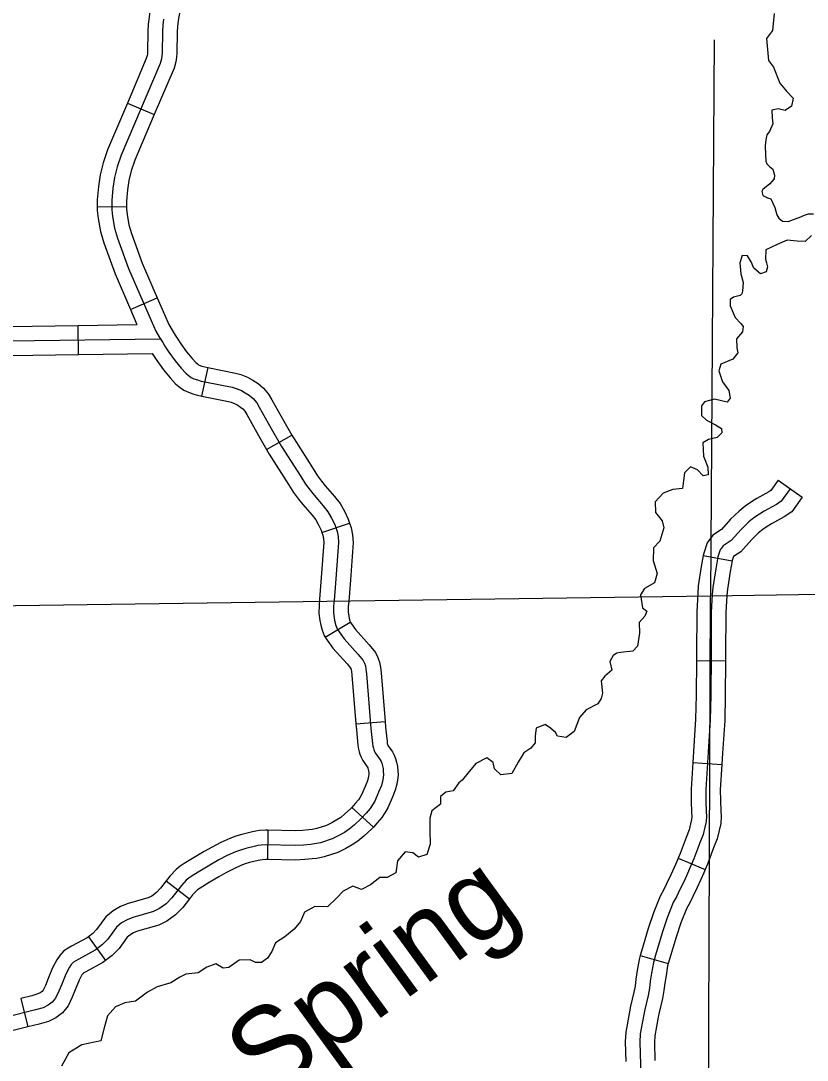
# Model space of a CAD drawing. Extents: x -492261 to -432772, y 1441225 to 1452922.
# Drawn here: x -458346.3 to -458231, y 1451481.9 to 1451634.2 of the extents above; entities that cross this region are included whole.
import ezdxf

# ---------------------------------------------------------------- set-up
doc = ezdxf.new("R2010")
doc.units = 0
doc.layers.add('Default', color=7, linetype='Continuous')

msp = doc.modelspace()

# ---------------------------------------------------------------- linework, layer by layer
at = {"layer": 'Default'}
for p, q in [((-458330.65, 1451622.14), (-458326.71, 1451620.45)), ((-458335.06, 1451606.95), (-458330.78, 1451606.97)), ((-458330.2, 1451591.87), (-458326.27, 1451593.57)), ((-458337.82, 1451585.27), (-458337.88, 1451589.56)), ((-458319.75, 1451579.19), (-458318.82, 1451583.37)), ((-458310.25, 1451571.35), (-458306.54, 1451573.48)), ((-458235.25, 1451566.86), (-458231.75, 1451564.38)), ((-458302.13, 1451559.2), (-458298.07, 1451560.57)), ((-458246.23, 1451555.82), (-458242.01, 1451555.05)), ((-458301.64, 1451543.85), (-458297.97, 1451546.08)), ((-458247.24, 1451540.43), (-458242.96, 1451540.39)), ((-458297.15, 1451531.15), (-458292.88, 1451531.5)), ((-458247.77, 1451525.48), (-458243.49, 1451525.2)), ((-458297.75, 1451518.91), (-458294.59, 1451516.02)), ((-458310.04, 1451515.55), (-458310.13, 1451511.27)), ((-458249.9, 1451511.46), (-458245.95, 1451509.8)), ((-458324.95, 1451508.13), (-458321.56, 1451505.5)), ((-458336.37, 1451499.93), (-458333.84, 1451496.48)), ((-458255.48, 1451497.21), (-458251.36, 1451496.03)), ((-458346.27, 1451490.91), (-458345.25, 1451486.75))]:
    msp.add_line(p, q, dxfattribs=at)
for points in [[(-458327.21, 1451636.18), (-458327.27, 1451635.9), (-458327.39, 1451635.26), (-458327.47, 1451634.71), (-458327.58, 1451633.7), (-458327.63, 1451632.69), (-458327.7, 1451629.6), (-458327.72, 1451629.3), (-458327.75, 1451629.09), (-458327.87, 1451628.65), (-458330.65, 1451622.14)], [(-458323.01, 1451635.29), (-458323.07, 1451635.04), (-458323.17, 1451634.53), (-458323.22, 1451634.17), (-458323.31, 1451633.38), (-458323.34, 1451632.55), (-458323.42, 1451629.45), (-458323.45, 1451628.84), (-458323.56, 1451628.18), (-458323.81, 1451627.24), (-458326.71, 1451620.45)], [(-458325.35, 1451634.44), (-458325.45, 1451633.54), (-458325.48, 1451632.62), (-458325.56, 1451629.52)], [(-458235.82, 1451635.25), (-458236.08, 1451632.75), (-458236.94, 1451631.62), (-458236.67, 1451628.39), (-458235.94, 1451627.4), (-458235.03, 1451625.07), (-458234.01, 1451623.88), (-458233.07, 1451622.84), (-458233.28, 1451621.66), (-458234.21, 1451621.07), (-458235.24, 1451621.31), (-458236.18, 1451621.09), (-458236.12, 1451619.95), (-458236.02, 1451619.09), (-458236.51, 1451617.99), (-458236.9, 1451617.47), (-458237.08, 1451616.75), (-458237.18, 1451615.86), (-458237.18, 1451615.71)], [(-458244.61, 1451631.4), (-458245.17, 1451549.93)], [(-458325.56, 1451629.52), (-458325.58, 1451629.07), (-458325.66, 1451628.63), (-458325.84, 1451627.94), (-458331.57, 1451614.52)], [(-458330.65, 1451622.14), (-458333.58, 1451615.27), (-458334.2, 1451613.37), (-458334.62, 1451611.64), (-458334.9, 1451609.93), (-458335.07, 1451607.94), (-458335.06, 1451606.95)], [(-458326.71, 1451620.45), (-458329.56, 1451613.77), (-458330.07, 1451612.2), (-458330.42, 1451610.78), (-458330.65, 1451609.41), (-458330.78, 1451607.77), (-458330.78, 1451606.97)], [(-458331.57, 1451614.52), (-458332.13, 1451612.79), (-458332.52, 1451611.21), (-458332.77, 1451609.67), (-458332.92, 1451607.86), (-458332.92, 1451606.51), (-458332.82, 1451605.53), (-458332.52, 1451603.82), (-458332.09, 1451602.33), (-458330.47, 1451597.88), (-458327.18, 1451590.27), (-458326.46, 1451588.72), (-458325.94, 1451587.79), (-458325.47, 1451587.03), (-458325.08, 1451586.38), (-458324.59, 1451585.63), (-458323.65, 1451584.35), (-458322.77, 1451583.28), (-458322.07, 1451582.55), (-458321.75, 1451582.25), (-458321.28, 1451581.91), (-458320.9, 1451581.74), (-458320.39, 1451581.56), (-458319.83, 1451581.4), (-458319.06, 1451581.23), (-458315.3, 1451580.48), (-458314.72, 1451580.31), (-458313.93, 1451580.01), (-458313.36, 1451579.69), (-458312.78, 1451579.31), (-458312.23, 1451578.84), (-458311.69, 1451578.22), (-458311.31, 1451577.58), (-458309.57, 1451574.46), (-458308.04, 1451571.8), (-458305.24, 1451567.39), (-458304.54, 1451566.3), (-458303.87, 1451565.39), (-458303.28, 1451564.66), (-458301.93, 1451563.11), (-458301.25, 1451562.24), (-458300.71, 1451561.31), (-458300.26, 1451560.35), (-458299.92, 1451559.36), (-458299.77, 1451558.59), (-458299.7, 1451557.73), (-458300.08, 1451552.41), (-458300.34, 1451549.25), (-458300.41, 1451548.45), (-458300.41, 1451547.47), (-458300.34, 1451546.64), (-458300.22, 1451546.09), (-458300.08, 1451545.56), (-458299.88, 1451545.09), (-458299.6, 1451544.62), (-458298.86, 1451543.61), (-458296.83, 1451541.34), (-458296.09, 1451540.44), (-458295.91, 1451540.07), (-458295.75, 1451539.64), (-458295.67, 1451539.17), (-458295.61, 1451538.47), (-458294.95, 1451530.46), (-458294.72, 1451528.28), (-458294.66, 1451527.86), (-458294.59, 1451527.6), (-458294.53, 1451527.37), (-458294.43, 1451527.12), (-458294.31, 1451526.89), (-458293.61, 1451525.88), (-458293.47, 1451525.64), (-458293.36, 1451525.37), (-458293.26, 1451525.01), (-458293.17, 1451524.6), (-458293.13, 1451524.17), (-458293.12, 1451523.71), (-458293.16, 1451523.22), (-458293.24, 1451522.76), (-458293.42, 1451522.12), (-458293.82, 1451521.12), (-458294.39, 1451519.81), (-458294.7, 1451519.27), (-458295.08, 1451518.73), (-458295.63, 1451518.05), (-458296.36, 1451517.26), (-458297.4, 1451516.29), (-458298.12, 1451515.7), (-458298.82, 1451515.25), (-458299.64, 1451514.78), (-458300.63, 1451514.29), (-458302.32, 1451513.73), (-458303.22, 1451513.56), (-458303.8, 1451513.49), (-458304.82, 1451513.39), (-458305.98, 1451513.32), (-458310.33, 1451513.42), (-458311.06, 1451513.37), (-458311.52, 1451513.3), (-458311.89, 1451513.24)], [(-458237.18, 1451615.71), (-458237.07, 1451613.62), (-458236.91, 1451613.25), (-458236.5, 1451612.83), (-458236.04, 1451612.44), (-458235.81, 1451611.56), (-458235.86, 1451611.04), (-458236.47, 1451610.28), (-458237.5, 1451609.48), (-458237.64, 1451609.16), (-458237.51, 1451608.59), (-458236.82, 1451608.26), (-458236.32, 1451608.08), (-458235.75, 1451606.83), (-458235.46, 1451605.75), (-458235.14, 1451605.27), (-458234.61, 1451604.85), (-458233.75, 1451604.78), (-458233.13, 1451605), (-458232.17, 1451605.37), (-458231.4, 1451605.7), (-458230.81, 1451605.89), (-458230.06, 1451605.91)], [(-458335.06, 1451606.95), (-458335.06, 1451606.39), (-458334.94, 1451605.23), (-458334.61, 1451603.33), (-458334.12, 1451601.67), (-458332.46, 1451597.09), (-458330.2, 1451591.87)], [(-458330.78, 1451606.97), (-458330.77, 1451606.62), (-458330.69, 1451605.82), (-458330.43, 1451604.3), (-458330.05, 1451603), (-458328.47, 1451598.67), (-458326.27, 1451593.57)], [(-458230.38, 1451602.75), (-458231.28, 1451601.83), (-458232.48, 1451601.89), (-458233.91, 1451602.03), (-458235.38, 1451601.39), (-458237.05, 1451600.63), (-458237.1, 1451599.25), (-458236.97, 1451598.74), (-458236.84, 1451598.14), (-458237.03, 1451597.42), (-458237.82, 1451597.11), (-458238.81, 1451597.92), (-458239.21, 1451598.86), (-458239.74, 1451599.73), (-458240.52, 1451599.8), (-458240.89, 1451598.7), (-458240.74, 1451597.13), (-458240.39, 1451595.82), (-458240.47, 1451594.58), (-458240.6, 1451594.18), (-458240.8, 1451593.91), (-458241.79, 1451593.69), (-458242.27, 1451593.36), (-458242.3, 1451592.41), (-458241.55, 1451590.71), (-458240.72, 1451589.81), (-458240.4, 1451589.39), (-458240.49, 1451588.59), (-458241.38, 1451587.59), (-458241.32, 1451586.24), (-458241.16, 1451585.53), (-458241.88, 1451584.62), (-458243.66, 1451583.86), (-458243.95, 1451582.91), (-458243.42, 1451581.26), (-458242.47, 1451580.02), (-458242.3, 1451578.91), (-458242.75, 1451578.32), (-458244.59, 1451578.74), (-458246.06, 1451578.33), (-458246.51, 1451577.77), (-458246.47, 1451576.37), (-458245.77, 1451575.64), (-458244.43, 1451574.98), (-458243.56, 1451574.46), (-458243.52, 1451573.8), (-458244.19, 1451573.1), (-458245.44, 1451572.84), (-458246.28, 1451572.33), (-458246.18, 1451570.41), (-458245.56, 1451568.76), (-458245.51, 1451567.67), (-458246.27, 1451567.51), (-458247.07, 1451568.38), (-458248.08, 1451568.81), (-458248.97, 1451567.96), (-458249.14, 1451566.81), (-458249.26, 1451565.66), (-458250.71, 1451565.48), (-458252.13, 1451564.96), (-458253.3, 1451563.69), (-458253.23, 1451562.12), (-458252.28, 1451560.91), (-458252.03, 1451559.86), (-458252.58, 1451557.92), (-458253.55, 1451556.95), (-458253.59, 1451555.09), (-458253, 1451553.18), (-458253.4, 1451551.82), (-458254.83, 1451551.01), (-458255.41, 1451550.08), (-458255.16, 1451548.16), (-458254.52, 1451547.66), (-458254.79, 1451546.94), (-458255.62, 1451546), (-458255.58, 1451544.45), (-458255.85, 1451542.53), (-458256.54, 1451541.79), (-458258.37, 1451541.63), (-458258.91, 1451541.5), (-458259.44, 1451541.18), (-458259.91, 1451540.3), (-458259.62, 1451539.02), (-458260.68, 1451538.13), (-458261.21, 1451537.46), (-458261.02, 1451535.66)], [(-458326.27, 1451593.57), (-458325.22, 1451591.15), (-458324.55, 1451589.69), (-458324.09, 1451588.87), (-458323.64, 1451588.14), (-458323.27, 1451587.51), (-458322.83, 1451586.85), (-458321.96, 1451585.66), (-458321.17, 1451584.7), (-458320.57, 1451584.08), (-458320.39, 1451583.91), (-458320.21, 1451583.78), (-458320.11, 1451583.73), (-458319.73, 1451583.6), (-458319.31, 1451583.48), (-458318.82, 1451583.37)], [(-458330.2, 1451591.87), (-458329.26, 1451589.68)], [(-458352.96, 1451589.34), (-458347.96, 1451589.41), (-458337.88, 1451589.56)], [(-458337.88, 1451589.56), (-458329.26, 1451589.68)], [(-458410.2, 1451575.22), (-458403.22, 1451580.02), (-458402.02, 1451580.8), (-458400.68, 1451581.37), (-458399.83, 1451581.69), (-458398.9, 1451581.96), (-458397.46, 1451582.27), (-458392.1, 1451583.36), (-458391.17, 1451583.61), (-458390.31, 1451583.87), (-458389.44, 1451584.26), (-458387.87, 1451584.99), (-458385.99, 1451586), (-458384.07, 1451587.06), (-458383.46, 1451587.37), (-458382.88, 1451587.6), (-458382.48, 1451587.73), (-458382.03, 1451587.79), (-458381, 1451587.85), (-458363.94, 1451587.3), (-458355.27, 1451587.17), (-458347.93, 1451587.27), (-458325.82, 1451587.59)], [(-458337.82, 1451585.27), (-458327.03, 1451585.43)], [(-458327.03, 1451585.43), (-458326.35, 1451584.41), (-458325.35, 1451583.03), (-458324.37, 1451581.85), (-458323.57, 1451581.01), (-458323.12, 1451580.6), (-458322.35, 1451580.04), (-458321.69, 1451579.75), (-458321.04, 1451579.51), (-458320.35, 1451579.32), (-458319.75, 1451579.19)], [(-458352.9, 1451585.06), (-458347.9, 1451585.12), (-458337.82, 1451585.27)], [(-458318.82, 1451583.37), (-458318.62, 1451583.33), (-458314.78, 1451582.56), (-458314.04, 1451582.34), (-458313.03, 1451581.96), (-458312.24, 1451581.52), (-458311.49, 1451581.02), (-458310.71, 1451580.36), (-458309.95, 1451579.48), (-458309.45, 1451578.65), (-458307.7, 1451575.51), (-458306.54, 1451573.48)], [(-458319.75, 1451579.19), (-458319.5, 1451579.13), (-458315.81, 1451578.4), (-458315.41, 1451578.28), (-458314.84, 1451578.06), (-458314.47, 1451577.86), (-458314.07, 1451577.59), (-458313.74, 1451577.31), (-458313.43, 1451576.96), (-458313.16, 1451576.5), (-458311.43, 1451573.4), (-458310.25, 1451571.35)], [(-458306.54, 1451573.48), (-458306.21, 1451572.91), (-458303.43, 1451568.55), (-458302.77, 1451567.51), (-458302.17, 1451566.7), (-458301.64, 1451566.04), (-458300.28, 1451564.48), (-458299.47, 1451563.44), (-458298.81, 1451562.31), (-458298.26, 1451561.15), (-458298.07, 1451560.57)], [(-458310.25, 1451571.35), (-458309.87, 1451570.69), (-458307.05, 1451566.24), (-458306.3, 1451565.08), (-458305.57, 1451564.09), (-458304.92, 1451563.28), (-458303.58, 1451561.75), (-458303.03, 1451561.04), (-458302.61, 1451560.32), (-458302.25, 1451559.55), (-458302.13, 1451559.2)], [(-458233.5, 1451565.62), (-458234.8, 1451563.78), (-458235.5, 1451563.31), (-458237.3, 1451562.31), (-458238.01, 1451561.9), (-458238.8, 1451561.36), (-458239.55, 1451560.74), (-458240.67, 1451559.65), (-458242.14, 1451558.01), (-458243.32, 1451557.23), (-458243.74, 1451556.68), (-458244.08, 1451555.64), (-458244.41, 1451553.85), (-458244.83, 1451551.14), (-458244.92, 1451550.11), (-458245.05, 1451547.53), (-458245.09, 1451541.33), (-458245.14, 1451535.34), (-458245.22, 1451531.75), (-458245.53, 1451526.98), (-458245.87, 1451521.53), (-458245.86, 1451519.89), (-458245.82, 1451518.26), (-458245.77, 1451517.6), (-458245.81, 1451516.85), (-458245.99, 1451516.02), (-458246.25, 1451514.95), (-458246.73, 1451513.73), (-458247.62, 1451511.36), (-458248.13, 1451510.14), (-458248.54, 1451509.22), (-458249.05, 1451508.08), (-458249.7, 1451506.78), (-458250.11, 1451505.91), (-458250.63, 1451504.98), (-458251.52, 1451502.72), (-458252.26, 1451500.52), (-458253.24, 1451497.26), (-458253.55, 1451496.16), (-458253.8, 1451494.63), (-458254, 1451493.45), (-458254.11, 1451492.39), (-458254.32, 1451491.35), (-458254.81, 1451489.3), (-458254.96, 1451488.55), (-458255.46, 1451485.7), (-458255.54, 1451484.5), (-458255.28, 1451476.27)], [(-458235.25, 1451566.86), (-458236.32, 1451565.34), (-458236.62, 1451565.14), (-458238.37, 1451564.17), (-458239.16, 1451563.7), (-458240.08, 1451563.08), (-458240.98, 1451562.34), (-458242.22, 1451561.13), (-458243.55, 1451559.65), (-458244.81, 1451558.82), (-458245.66, 1451557.68), (-458246.16, 1451556.17), (-458246.23, 1451555.82)], [(-458231.75, 1451564.38), (-458233.27, 1451562.23), (-458234.38, 1451561.48), (-458236.24, 1451560.45), (-458236.86, 1451560.09), (-458237.51, 1451559.64), (-458238.12, 1451559.14), (-458239.12, 1451558.17), (-458240.73, 1451556.37), (-458241.82, 1451555.66), (-458242, 1451555.1), (-458242.01, 1451555.05)], [(-458298.07, 1451560.57), (-458297.85, 1451559.9), (-458297.65, 1451558.88), (-458297.55, 1451557.73), (-458297.95, 1451552.25), (-458298.21, 1451549.07), (-458298.27, 1451548.35), (-458298.27, 1451547.57), (-458298.21, 1451546.96), (-458298.13, 1451546.58), (-458298.05, 1451546.26), (-458297.97, 1451546.07), (-458297.97, 1451546.08)], [(-458302.13, 1451559.2), (-458302, 1451558.81), (-458301.9, 1451558.29), (-458301.85, 1451557.72), (-458302.22, 1451552.58), (-458302.48, 1451549.43), (-458302.55, 1451548.54), (-458302.56, 1451547.37), (-458302.46, 1451546.32), (-458302.31, 1451545.6), (-458302.11, 1451544.86), (-458301.79, 1451544.11), (-458301.64, 1451543.85)], [(-458246.23, 1451555.82), (-458246.52, 1451554.21), (-458246.96, 1451551.4), (-458247.05, 1451550.26), (-458247.19, 1451547.59), (-458247.24, 1451541.35), (-458247.24, 1451540.43)], [(-458242.01, 1451555.05), (-458242.3, 1451553.49), (-458242.7, 1451550.89), (-458242.78, 1451549.96), (-458242.91, 1451547.46), (-458242.95, 1451541.32), (-458242.96, 1451540.39)], [(-458686.04, 1451548.16), (-458545.7, 1451551.4), (-458396.3, 1451547.82), (-458245.17, 1451549.93), (-458096.72, 1451552.17), (-457948.01, 1451552.92)], [(-458245.97, 1451139.54), (-458246.91, 1451249.54), (-458245.74, 1451399.02), (-458245.17, 1451549.93)], [(-458297.97, 1451546.08), (-458297.81, 1451545.81), (-458297.19, 1451544.96), (-458295.2, 1451542.73), (-458294.27, 1451541.61), (-458293.93, 1451540.9), (-458293.67, 1451540.19), (-458293.54, 1451539.45), (-458293.47, 1451538.65), (-458292.88, 1451531.5)], [(-458301.64, 1451543.85), (-458301.38, 1451543.43), (-458300.52, 1451542.26), (-458298.45, 1451539.94), (-458297.9, 1451539.27), (-458297.88, 1451539.23), (-458297.83, 1451539.09), (-458297.8, 1451538.89), (-458297.74, 1451538.29), (-458297.15, 1451531.15)], [(-458247.24, 1451540.43), (-458247.28, 1451535.37), (-458247.36, 1451531.84), (-458247.67, 1451527.12), (-458247.77, 1451525.48)], [(-458242.96, 1451540.39), (-458243, 1451535.3), (-458243.08, 1451531.66), (-458243.39, 1451526.85), (-458243.49, 1451525.2)], [(-458261.02, 1451535.66), (-458261.2, 1451534.85), (-458261.69, 1451534.09), (-458263.42, 1451533.19), (-458264.36, 1451532.08), (-458265.14, 1451530.05), (-458266.32, 1451529.13), (-458267.61, 1451529.33), (-458267.91, 1451529.9), (-458268.61, 1451530.54), (-458269.42, 1451531.06), (-458270.73, 1451530.52), (-458270.87, 1451529.42), (-458270.87, 1451528.39), (-458271.51, 1451527.57), (-458272.52, 1451526.92), (-458273.35, 1451525.55), (-458274.28, 1451523.89), (-458275.9, 1451523.68), (-458276.81, 1451524.57), (-458277.03, 1451525.51), (-458277.94, 1451526.18), (-458279.58, 1451525.36), (-458280.74, 1451523.93), (-458281.57, 1451522.91), (-458282.08, 1451522.52), (-458282.9, 1451521.35), (-458283.99, 1451521.15), (-458284.74, 1451520.5), (-458284.74, 1451519.36), (-458286, 1451518.41), (-458286.32, 1451517.34), (-458286.3, 1451515.48), (-458286.28, 1451513.53), (-458286.76, 1451512.02), (-458287.95, 1451511.62), (-458288.79, 1451512.23), (-458289.94, 1451512.4), (-458291.05, 1451511.06), (-458291.29, 1451509.3), (-458292.59, 1451508.61), (-458293.65, 1451508.64), (-458294.99, 1451507.57), (-458296.32, 1451506.88), (-458297.59, 1451507.34), (-458299, 1451506.64), (-458299.98, 1451505.59), (-458301.29, 1451504.35), (-458303.18, 1451504.39), (-458304.7, 1451503.55), (-458305.29, 1451502.19), (-458306.18, 1451501.07), (-458307.55, 1451499.92), (-458308.93, 1451499.06), (-458309.47, 1451497.78), (-458310.13, 1451496.79), (-458311, 1451496.17), (-458311.89, 1451496.17), (-458312.64, 1451496.56), (-458314.25, 1451496.54), (-458315.79, 1451495.45), (-458316.59, 1451495.34), (-458317.69, 1451495.97), (-458319.02, 1451495.51), (-458320.26, 1451494.67), (-458322.09, 1451494.46), (-458322.96, 1451494.03), (-458324.26, 1451493.2), (-458326.3, 1451492.6), (-458327.71, 1451491.85), (-458329.45, 1451490.49), (-458331.02, 1451490.28), (-458332.4, 1451489.7), (-458333.54, 1451488.35), (-458334.07, 1451486.62), (-458334.53, 1451484.69), (-458337.32, 1451484.1), (-458339.21, 1451482.93), (-458340.3, 1451480.99)], [(-458297.15, 1451531.15), (-458297.08, 1451530.26), (-458296.85, 1451528.01), (-458296.76, 1451527.45), (-458296.66, 1451527.04), (-458296.56, 1451526.7), (-458296.4, 1451526.25), (-458296.15, 1451525.78), (-458295.41, 1451524.72), (-458295.41, 1451524.71), (-458295.39, 1451524.67), (-458295.33, 1451524.48), (-458295.29, 1451524.27), (-458295.27, 1451524.04), (-458295.26, 1451523.78), (-458295.29, 1451523.49), (-458295.33, 1451523.23), (-458295.45, 1451522.82), (-458295.8, 1451521.95), (-458296.31, 1451520.76), (-458296.51, 1451520.42), (-458296.78, 1451520.03), (-458297.25, 1451519.46), (-458297.75, 1451518.91)], [(-458292.88, 1451531.5), (-458292.81, 1451530.66), (-458292.59, 1451528.56), (-458292.55, 1451528.28), (-458292.52, 1451528.15), (-458292.49, 1451528.05), (-458292.47, 1451528), (-458291.8, 1451527.04), (-458291.53, 1451526.58), (-458291.34, 1451526.06), (-458291.18, 1451525.55), (-458291.05, 1451524.92), (-458290.99, 1451524.29), (-458290.97, 1451523.64), (-458291.03, 1451522.95), (-458291.14, 1451522.29), (-458291.39, 1451521.42), (-458291.85, 1451520.3), (-458292.47, 1451518.85), (-458292.89, 1451518.12), (-458293.37, 1451517.43), (-458294.01, 1451516.65), (-458294.59, 1451516.02)], [(-458247.77, 1451525.48), (-458248.02, 1451521.59), (-458248, 1451519.86), (-458247.96, 1451518.16), (-458247.92, 1451517.58), (-458247.94, 1451517.13), (-458248.08, 1451516.49), (-458248.3, 1451515.6), (-458248.73, 1451514.5), (-458249.61, 1451512.15), (-458249.9, 1451511.46)], [(-458243.49, 1451525.2), (-458243.73, 1451521.47), (-458243.72, 1451519.93), (-458243.68, 1451518.36), (-458243.63, 1451517.62), (-458243.68, 1451516.57), (-458243.9, 1451515.54), (-458244.2, 1451514.3), (-458244.73, 1451512.96), (-458245.63, 1451510.57), (-458245.95, 1451509.8)], [(-458297.75, 1451518.91), (-458297.88, 1451518.77), (-458298.81, 1451517.9), (-458299.38, 1451517.44), (-458299.93, 1451517.09), (-458300.66, 1451516.67), (-458301.45, 1451516.27), (-458302.86, 1451515.81), (-458303.54, 1451515.68), (-458304.03, 1451515.62), (-458304.99, 1451515.52), (-458306.01, 1451515.47), (-458310.04, 1451515.55)], [(-458310.04, 1451515.55), (-458310.38, 1451515.56), (-458311.28, 1451515.5), (-458311.84, 1451515.42), (-458312.33, 1451515.34), (-458313.87, 1451514.96), (-458314.75, 1451514.69), (-458315.64, 1451514.37), (-458316.96, 1451513.76), (-458318.24, 1451513.08), (-458319.38, 1451512.46), (-458320.88, 1451511.55), (-458322.32, 1451510.67), (-458322.9, 1451510.28), (-458323.49, 1451509.8), (-458324.36, 1451508.88), (-458324.95, 1451508.13)], [(-458294.59, 1451516.02), (-458294.83, 1451515.75), (-458295.99, 1451514.67), (-458296.86, 1451513.96), (-458297.71, 1451513.42), (-458298.63, 1451512.89), (-458299.81, 1451512.3), (-458301.79, 1451511.65), (-458302.9, 1451511.44), (-458303.57, 1451511.36), (-458304.65, 1451511.25), (-458305.94, 1451511.18), (-458310.13, 1451511.27)], [(-458311.89, 1451513.24), (-458313.3, 1451512.9), (-458314.07, 1451512.66), (-458314.82, 1451512.39), (-458316.01, 1451511.84), (-458317.22, 1451511.2), (-458318.31, 1451510.6), (-458319.77, 1451509.72), (-458321.15, 1451508.87), (-458321.62, 1451508.55), (-458322.04, 1451508.22), (-458322.73, 1451507.48), (-458324.14, 1451505.67), (-458324.98, 1451504.79), (-458325.96, 1451504.08), (-458326.81, 1451503.66), (-458329.85, 1451502.78), (-458330.7, 1451502.44), (-458331.51, 1451501.97), (-458332.24, 1451501.37), (-458333.51, 1451499.62), (-458334.29, 1451498.8), (-458335.39, 1451498), (-458337.78, 1451496.68), (-458338.22, 1451496.44), (-458338.55, 1451496.23), (-458338.88, 1451495.86), (-458339.14, 1451495.48), (-458339.67, 1451494.48), (-458340.27, 1451493), (-458340.7, 1451491.96), (-458341.16, 1451490.97), (-458341.66, 1451490.37), (-458342.27, 1451489.91), (-458342.98, 1451489.55), (-458344.12, 1451489.24), (-458348.38, 1451488.18)], [(-458310.13, 1451511.27), (-458310.28, 1451511.27), (-458310.84, 1451511.23), (-458311.19, 1451511.19), (-458311.46, 1451511.14), (-458312.74, 1451510.83), (-458313.39, 1451510.63), (-458314, 1451510.41), (-458315.06, 1451509.92), (-458316.21, 1451509.31), (-458317.24, 1451508.74), (-458318.65, 1451507.89), (-458319.99, 1451507.07), (-458320.35, 1451506.82), (-458320.58, 1451506.64), (-458321.11, 1451506.09), (-458321.56, 1451505.5)], [(-458249.9, 1451511.46), (-458250.1, 1451510.99), (-458250.49, 1451510.09), (-458250.98, 1451509.01), (-458251.63, 1451507.71), (-458252.02, 1451506.89), (-458252.57, 1451505.9), (-458253.53, 1451503.45), (-458254.3, 1451501.17), (-458255.29, 1451497.86), (-458255.48, 1451497.21)], [(-458245.95, 1451509.8), (-458246.16, 1451509.3), (-458246.58, 1451508.34), (-458247.12, 1451507.16), (-458247.77, 1451505.85), (-458248.2, 1451504.93), (-458248.69, 1451504.06), (-458249.5, 1451501.98), (-458250.22, 1451499.87), (-458251.18, 1451496.65), (-458251.36, 1451496.03)], [(-458324.95, 1451508.13), (-458325.77, 1451507.07), (-458326.39, 1451506.42), (-458327.08, 1451505.92), (-458327.59, 1451505.66), (-458330.54, 1451504.81), (-458331.65, 1451504.37), (-458332.74, 1451503.73), (-458333.81, 1451502.86), (-458335.16, 1451500.99), (-458335.71, 1451500.41), (-458336.37, 1451499.93)], [(-458321.56, 1451505.5), (-458322.52, 1451504.26), (-458323.57, 1451503.17), (-458324.85, 1451502.24), (-458326.03, 1451501.65), (-458329.15, 1451500.75), (-458329.76, 1451500.51), (-458330.29, 1451500.2), (-458330.67, 1451499.89), (-458331.86, 1451498.25), (-458332.87, 1451497.18), (-458333.84, 1451496.48)], [(-458336.37, 1451499.93), (-458336.54, 1451499.81), (-458338.82, 1451498.55), (-458339.32, 1451498.28), (-458339.94, 1451497.88), (-458340.57, 1451497.19), (-458340.98, 1451496.58), (-458341.62, 1451495.39), (-458342.25, 1451493.81), (-458342.66, 1451492.82), (-458342.98, 1451492.13), (-458343.14, 1451491.94), (-458343.41, 1451491.74), (-458343.76, 1451491.56), (-458344.66, 1451491.31), (-458346.27, 1451490.91)], [(-458255.48, 1451497.21), (-458255.65, 1451496.63), (-458255.91, 1451494.98), (-458256.12, 1451493.75), (-458256.23, 1451492.71), (-458256.41, 1451491.81), (-458256.9, 1451489.77), (-458257.06, 1451488.95), (-458257.59, 1451485.96), (-458257.69, 1451484.54), (-458257.59, 1451481.67)], [(-458333.84, 1451496.48), (-458334.23, 1451496.19), (-458336.75, 1451494.8), (-458337.12, 1451494.6), (-458337.15, 1451494.58), (-458337.19, 1451494.53), (-458337.3, 1451494.37), (-458337.73, 1451493.57), (-458338.28, 1451492.19), (-458338.73, 1451491.1), (-458339.33, 1451489.81), (-458340.18, 1451488.8), (-458341.14, 1451488.09), (-458342.2, 1451487.54), (-458343.57, 1451487.16), (-458345.25, 1451486.75)], [(-458251.36, 1451496.03), (-458251.46, 1451495.69), (-458251.68, 1451494.28), (-458251.87, 1451493.16), (-458251.99, 1451492.07), (-458252.22, 1451490.9), (-458252.71, 1451488.84), (-458252.85, 1451488.16), (-458253.33, 1451485.44), (-458253.4, 1451484.46), (-458253.31, 1451481.81)], [(-458345.25, 1451486.75), (-458347.79, 1451486.12), (-458350.73, 1451485.18), (-458359.31, 1451482.44), (-458359.73, 1451482.35)]]:
    msp.add_lwpolyline(points, dxfattribs=at)

# ---------------------------------------------------------------- texts
msp.add_text('Spring', height=12.069, rotation=36.064, dxfattribs=at).set_placement((-458310.37, 1451475.78))

doc.saveas('drawing.dxf')
